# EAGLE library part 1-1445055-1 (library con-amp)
Micro MATE-N-LOK Connectors grid 1.5 mm Source: ENG_CD_1445055_A.pdf
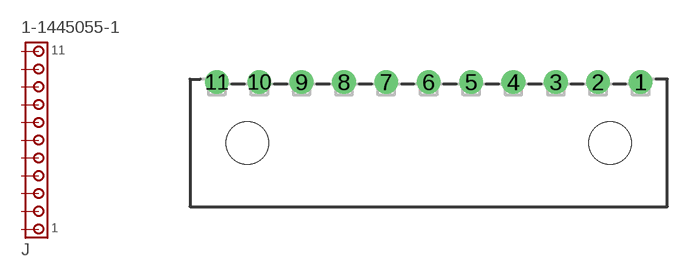
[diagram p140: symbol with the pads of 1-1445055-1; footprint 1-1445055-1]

Designator prefix J

## 1-1445055-1 (MF: TYCO ELECTRONICS; MPN: 1-1445055-1; OC_FARNELL: unknown; OC_NEWARK: 09H5354)  [1-1445055-1]
1  1  pas
2  2  pas
3  3  pas
4  4  pas
5  5  pas
6  6  pas
7  7  pas
8  8  pas
9  9  pas
10  10  pas
11  11  pas

## Footprint 1-1445055-1 (pad centres in mm)
Micro MATE-N-LOK Connectors grid 1.5 mm Source: ENG_CD_1445055_A.pdf
drill 1 pad 1.676 round: 1 15,4.32; 2 12,4.32; 3 9,4.32; 4 6,4.32; 5 3,4.32; 6 0,4.32; 7 -3,4.32; 8 -6,4.32; 9 -9,4.32; 10 -12,4.32; 11 -15,4.32
hole 3 at -12.85,0
hole 3 at 12.85,0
